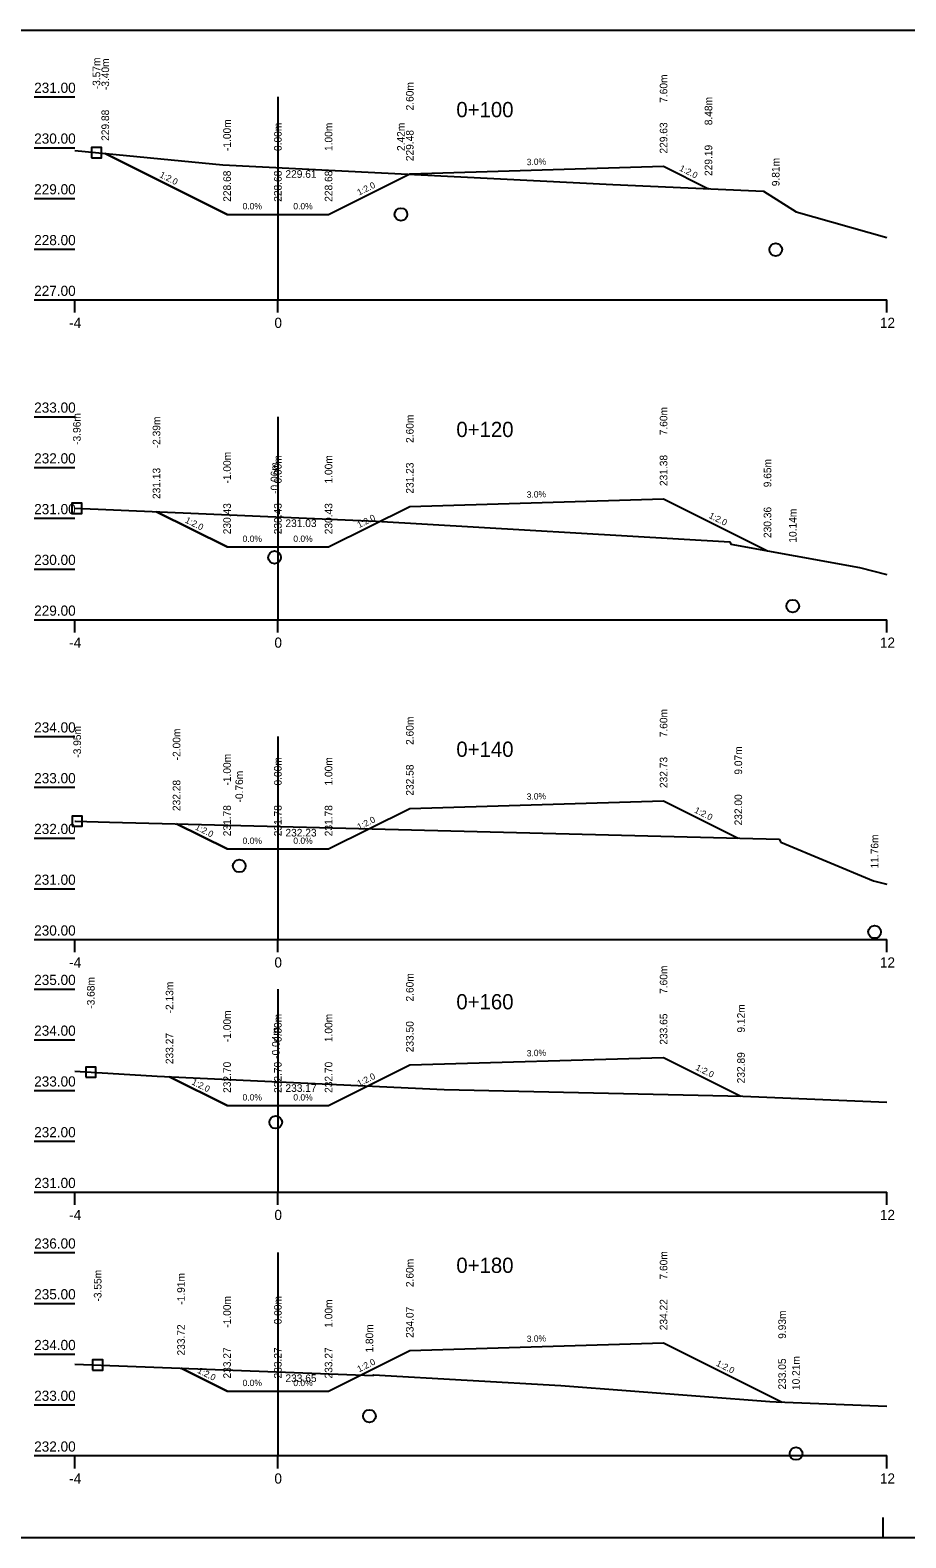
# Model space of a CAD drawing. Extents: x -578374 to -578229, y -1159997 to -1159967.
# Drawn here: x -578329.74 to -578312.48, y -1159996.88 to -1159967.18 of the extents above; entities that cross this region are included whole.
import ezdxf

# ---------------------------------------------------------------- set-up
doc = ezdxf.new("R2010")
doc.units = 0
for name, color, linetype in [('16', 7, 'Continuous'), ('21', 7, 'Continuous'), ('28', 7, 'Continuous'), ('59', 7, 'Continuous'), ('Body pricny rez', 7, 'Continuous'), ('Hranice_pozemku', 7, 'Continuous'), ('Popis pricneho profilu', 7, 'Continuous'), ('Rámy', 7, 'Continuous')]:
    doc.layers.add(name, color=color, linetype=linetype)

msp = doc.modelspace()

# ---------------------------------------------------------------- linework, layer by layer
for points in [[(-578328.857, -1159969.556), (-578325.939, -1159969.837), (-578318.26, -1159970.224), (-578315.291, -1159970.353), (-578314.648, -1159970.762), (-578312.857, -1159971.268)], [(-578328.256, -1159969.614), (-578325.857, -1159970.814), (-578324.857, -1159970.814), (-578323.857, -1159970.814), (-578322.257, -1159970.014), (-578317.257, -1159969.864), (-578316.373, -1159970.306)], [(-578325.857, -1159970.814), (-578328.256, -1159969.614)], [(-578323.857, -1159970.814), (-578322.257, -1159970.014), (-578317.257, -1159969.864)], [(-578317.257, -1159969.864), (-578316.373, -1159970.306)], [(-578316.373, -1159970.306), (-578316.373, -1159970.305), (-578316.373, -1159970.306), (-578316.373, -1159970.306), (-578316.373, -1159970.306), (-578316.372, -1159970.306), (-578316.373, -1159970.306), (-578316.372, -1159970.305)], [(-578325.857, -1159970.814), (-578324.857, -1159970.814), (-578323.857, -1159970.814)], [(-578327.247, -1159976.669), (-578325.857, -1159977.364), (-578324.857, -1159977.364), (-578323.857, -1159977.364), (-578322.257, -1159976.564), (-578317.257, -1159976.414), (-578315.21, -1159977.438)], [(-578323.857, -1159977.364), (-578322.257, -1159976.564), (-578317.257, -1159976.414)], [(-578317.257, -1159976.414), (-578315.21, -1159977.438)], [(-578328.857, -1159976.601), (-578322.922, -1159976.853), (-578315.955, -1159977.263), (-578315.93, -1159977.306), (-578313.396, -1159977.769), (-578312.857, -1159977.907)], [(-578325.857, -1159977.364), (-578327.247, -1159976.669)], [(-578325.857, -1159977.364), (-578324.857, -1159977.364), (-578323.857, -1159977.364)], [(-578315.21, -1159977.438), (-578315.211, -1159977.437), (-578315.21, -1159977.438), (-578315.211, -1159977.438), (-578315.21, -1159977.438), (-578315.21, -1159977.438), (-578315.21, -1159977.438), (-578315.21, -1159977.437)], [(-578326.852, -1159982.816), (-578325.857, -1159983.313), (-578324.857, -1159983.313), (-578323.857, -1159983.313), (-578322.257, -1159982.513), (-578317.257, -1159982.363), (-578315.785, -1159983.099)], [(-578323.857, -1159983.313), (-578322.257, -1159982.513), (-578317.257, -1159982.363)], [(-578317.257, -1159982.363), (-578315.785, -1159983.099)], [(-578328.857, -1159982.763), (-578328.845, -1159982.764), (-578328.17, -1159982.782), (-578314.983, -1159983.12), (-578314.982, -1159983.121), (-578314.945, -1159983.18), (-578313.121, -1159983.942), (-578312.857, -1159984.006)], [(-578325.857, -1159983.313), (-578326.852, -1159982.816)], [(-578315.785, -1159983.099), (-578315.786, -1159983.099), (-578315.785, -1159983.099), (-578315.786, -1159983.1), (-578315.785, -1159983.099), (-578315.785, -1159983.1), (-578315.785, -1159983.099), (-578315.785, -1159983.099)], [(-578325.857, -1159983.313), (-578324.857, -1159983.313), (-578323.857, -1159983.313)], [(-578326.991, -1159987.801), (-578325.857, -1159988.368), (-578324.857, -1159988.368), (-578323.857, -1159988.368), (-578322.257, -1159987.568), (-578317.257, -1159987.418), (-578315.732, -1159988.18)], [(-578323.857, -1159988.368), (-578322.257, -1159987.568), (-578317.257, -1159987.418)], [(-578317.257, -1159987.418), (-578315.732, -1159988.18)], [(-578328.857, -1159987.691), (-578327.236, -1159987.79), (-578321.578, -1159988.048), (-578315.696, -1159988.181), (-578312.857, -1159988.299)], [(-578325.857, -1159988.368), (-578326.991, -1159987.801)], [(-578325.857, -1159988.368), (-578324.857, -1159988.368), (-578323.857, -1159988.368)], [(-578315.732, -1159988.18), (-578315.733, -1159988.18), (-578315.732, -1159988.18), (-578315.733, -1159988.181), (-578315.732, -1159988.18), (-578315.732, -1159988.181), (-578315.732, -1159988.18), (-578315.732, -1159988.18)], [(-578326.764, -1159993.541), (-578325.857, -1159993.994), (-578324.857, -1159993.994), (-578323.857, -1159993.994), (-578322.257, -1159993.194), (-578317.257, -1159993.044), (-578314.922, -1159994.212)], [(-578323.857, -1159993.994), (-578322.257, -1159993.194), (-578317.257, -1159993.044)], [(-578317.257, -1159993.044), (-578314.922, -1159994.212)], [(-578328.857, -1159993.46), (-578322.98, -1159993.687), (-578322.973, -1159993.675), (-578319.279, -1159993.88), (-578315.161, -1159994.198), (-578315.041, -1159994.207), (-578312.857, -1159994.288)], [(-578325.857, -1159993.994), (-578326.764, -1159993.541)], [(-578325.857, -1159993.994), (-578324.857, -1159993.994), (-578323.857, -1159993.994)], [(-578314.922, -1159994.212), (-578314.923, -1159994.211), (-578314.922, -1159994.212), (-578314.923, -1159994.212), (-578314.922, -1159994.212), (-578314.922, -1159994.212), (-578314.922, -1159994.212), (-578314.922, -1159994.211)]]:
    msp.add_lwpolyline(points)
for centre in [(-578322.432, -1159970.814), (-578315.048, -1159971.507), (-578324.922, -1159977.568), (-578314.712, -1159978.529), (-578325.617, -1159983.647), (-578313.1, -1159984.947), (-578324.897, -1159988.697), (-578323.052, -1159994.484), (-578314.648, -1159995.222)]:
    msp.add_circle(centre, 0.125)
at = {"layer": '16'}
for p, q in [((-578328.857, -1159972.498), (-578312.857, -1159972.498)), ((-578328.857, -1159978.798), (-578312.857, -1159978.798)), ((-578328.857, -1159985.098), (-578312.857, -1159985.098)), ((-578328.857, -1159990.072), (-578312.857, -1159990.072)), ((-578328.857, -1159995.264), (-578312.857, -1159995.264))]:
    msp.add_line(p, q, dxfattribs=at)
at = {"layer": '21'}
for p, q in [((-578329.657, -1159968.498), (-578328.857, -1159968.498)), ((-578329.657, -1159969.498), (-578328.857, -1159969.498)), ((-578329.657, -1159970.498), (-578328.857, -1159970.498)), ((-578329.657, -1159971.498), (-578328.857, -1159971.498)), ((-578329.657, -1159972.498), (-578328.857, -1159972.498)), ((-578329.657, -1159974.798), (-578328.857, -1159974.798)), ((-578329.657, -1159975.798), (-578328.857, -1159975.798)), ((-578329.657, -1159976.798), (-578328.857, -1159976.798)), ((-578329.657, -1159977.798), (-578328.857, -1159977.798)), ((-578329.657, -1159978.798), (-578328.857, -1159978.798)), ((-578329.657, -1159981.098), (-578328.857, -1159981.098)), ((-578329.657, -1159982.098), (-578328.857, -1159982.098)), ((-578329.657, -1159983.098), (-578328.857, -1159983.098)), ((-578329.657, -1159984.098), (-578328.857, -1159984.098)), ((-578329.657, -1159985.098), (-578328.857, -1159985.098)), ((-578329.657, -1159986.072), (-578328.857, -1159986.072)), ((-578329.657, -1159987.072), (-578328.857, -1159987.072)), ((-578329.657, -1159988.072), (-578328.857, -1159988.072)), ((-578329.657, -1159989.072), (-578328.857, -1159989.072)), ((-578329.657, -1159990.072), (-578328.857, -1159990.072)), ((-578329.657, -1159991.264), (-578328.857, -1159991.264)), ((-578329.657, -1159992.264), (-578328.857, -1159992.264)), ((-578329.657, -1159993.264), (-578328.857, -1159993.264)), ((-578329.657, -1159994.264), (-578328.857, -1159994.264)), ((-578329.657, -1159995.264), (-578328.857, -1159995.264))]:
    msp.add_line(p, q, dxfattribs=at)
at = {"layer": '28'}
for p, q in [((-578324.857, -1159968.498), (-578324.857, -1159972.498)), ((-578324.857, -1159974.798), (-578324.857, -1159978.798)), ((-578324.857, -1159981.098), (-578324.857, -1159985.098)), ((-578324.857, -1159986.072), (-578324.857, -1159990.072)), ((-578324.857, -1159991.264), (-578324.857, -1159995.264))]:
    msp.add_line(p, q, dxfattribs=at)
at = {"layer": '59'}
for p, q in [((-578328.857, -1159972.748), (-578328.857, -1159972.498)), ((-578324.857, -1159972.748), (-578324.857, -1159972.498)), ((-578312.857, -1159972.748), (-578312.857, -1159972.498)), ((-578328.857, -1159979.048), (-578328.857, -1159978.798)), ((-578324.857, -1159979.048), (-578324.857, -1159978.798)), ((-578312.857, -1159979.048), (-578312.857, -1159978.798)), ((-578328.857, -1159985.348), (-578328.857, -1159985.098)), ((-578324.857, -1159985.348), (-578324.857, -1159985.098)), ((-578312.857, -1159985.348), (-578312.857, -1159985.098)), ((-578328.857, -1159990.322), (-578328.857, -1159990.072)), ((-578324.857, -1159990.322), (-578324.857, -1159990.072)), ((-578312.857, -1159990.322), (-578312.857, -1159990.072)), ((-578328.857, -1159995.514), (-578328.857, -1159995.264)), ((-578324.857, -1159995.514), (-578324.857, -1159995.264)), ((-578312.857, -1159995.514), (-578312.857, -1159995.264))]:
    msp.add_line(p, q, dxfattribs=at)
at = {"layer": 'Hranice_pozemku'}
for points in [[(-578328.53, -1159969.697), (-578328.33, -1159969.697), (-578328.33, -1159969.497), (-578328.53, -1159969.497)], [(-578328.916, -1159976.702), (-578328.716, -1159976.702), (-578328.716, -1159976.502), (-578328.916, -1159976.502)], [(-578328.909, -1159982.865), (-578328.709, -1159982.865), (-578328.709, -1159982.665), (-578328.909, -1159982.665)], [(-578328.641, -1159987.81), (-578328.441, -1159987.81), (-578328.441, -1159987.61), (-578328.641, -1159987.61)], [(-578328.506, -1159993.578), (-578328.306, -1159993.578), (-578328.306, -1159993.378), (-578328.506, -1159993.378)]]:
    msp.add_lwpolyline(points, close=True, dxfattribs=at)
at = {"layer": 'Rámy'}
msp.add_line((-578312.93, -1159996.883), (-578312.93, -1159996.483), dxfattribs=at)
msp.add_lwpolyline([(-578373.807, -1159967.183), (-578228.93, -1159967.183), (-578228.93, -1159996.883), (-578373.807, -1159996.883)], close=True, dxfattribs=at)

# ---------------------------------------------------------------- texts
for s, height, p in [('0+100', 0.3, (-578321.34, -1159968.898)), ('+', 0.001, (-578324.858, -1159970.814)), ('0+120', 0.3, (-578321.34, -1159975.198)), ('+', 0.001, (-578324.858, -1159977.365)), ('0+140', 0.3, (-578321.34, -1159981.498)), ('+', 0.001, (-578324.858, -1159983.314)), ('0+160', 0.3, (-578321.34, -1159986.472)), ('+', 0.001, (-578324.858, -1159988.368)), ('0+180', 0.3, (-578321.34, -1159991.664)), ('+', 0.001, (-578324.858, -1159993.995))]:
    msp.add_text(s, height=height).set_placement(p)
for rotation, p in [(333.4349, (-578327.199, -1159970.073)), (333.4349, (-578316.957, -1159969.944)), (26.5651, (-578323.255, -1159970.443)), (333.4349, (-578326.694, -1159976.876)), (26.5651, (-578323.255, -1159976.993)), (333.4349, (-578316.376, -1159976.785)), (333.4349, (-578316.663, -1159982.59)), (26.5651, (-578323.255, -1159982.942)), (333.4349, (-578326.497, -1159982.923)), (26.5651, (-578323.255, -1159987.997)), (333.4349, (-578316.637, -1159987.658)), (333.4349, (-578326.566, -1159987.943)), (26.5651, (-578323.255, -1159993.623)), (333.4349, (-578316.232, -1159993.487)), (333.4349, (-578326.452, -1159993.627))]:
    msp.add_text('1:2.0', height=0.125, rotation=rotation).set_placement(p)
at = {"layer": '16'}
for s, rotation, p in [('3.0%', 1.7184, (-578319.951, -1159969.844)), ('0.0%', 360, (-578325.551, -1159970.714)), ('0.0%', 360, (-578324.551, -1159970.714)), ('3.0%', 1.7184, (-578319.951, -1159976.395)), ('0.0%', 360, (-578325.551, -1159977.264)), ('0.0%', 360, (-578324.551, -1159977.264)), ('3.0%', 1.7184, (-578319.951, -1159982.344)), ('0.0%', 360, (-578325.551, -1159983.213)), ('0.0%', 360, (-578324.551, -1159983.213)), ('3.0%', 1.7184, (-578319.951, -1159987.399)), ('0.0%', 360, (-578325.551, -1159988.268)), ('0.0%', 360, (-578324.551, -1159988.268)), ('3.0%', 1.7184, (-578319.951, -1159993.025)), ('0.0%', 360, (-578325.551, -1159993.894)), ('0.0%', 360, (-578324.551, -1159993.894))]:
    msp.add_text(s, height=0.125, rotation=rotation, dxfattribs=at).set_placement(p)
at = {"layer": '21'}
for s, p in [('231.00', (-578329.657, -1159968.418)), ('230.00', (-578329.657, -1159969.418)), ('229.00', (-578329.657, -1159970.418)), ('228.00', (-578329.657, -1159971.418)), ('227.00', (-578329.657, -1159972.418)), ('-4', (-578328.967, -1159973.048)), ('0', (-578324.924, -1159973.048)), ('12', (-578312.995, -1159973.048)), ('233.00', (-578329.657, -1159974.718)), ('232.00', (-578329.657, -1159975.718)), ('231.00', (-578329.657, -1159976.718)), ('230.00', (-578329.657, -1159977.718)), ('229.00', (-578329.657, -1159978.718)), ('-4', (-578328.967, -1159979.348)), ('0', (-578324.924, -1159979.348)), ('12', (-578312.995, -1159979.348)), ('234.00', (-578329.657, -1159981.018)), ('233.00', (-578329.657, -1159982.018)), ('232.00', (-578329.657, -1159983.018)), ('231.00', (-578329.657, -1159984.018)), ('230.00', (-578329.657, -1159985.018)), ('-4', (-578328.967, -1159985.648)), ('0', (-578324.924, -1159985.648)), ('12', (-578312.995, -1159985.648)), ('235.00', (-578329.657, -1159985.992)), ('234.00', (-578329.657, -1159986.992)), ('233.00', (-578329.657, -1159987.992)), ('232.00', (-578329.657, -1159988.992)), ('231.00', (-578329.657, -1159989.992)), ('-4', (-578328.967, -1159990.622)), ('0', (-578324.924, -1159990.622)), ('12', (-578312.995, -1159990.622)), ('236.00', (-578329.657, -1159991.184)), ('235.00', (-578329.657, -1159992.184)), ('234.00', (-578329.657, -1159993.184)), ('233.00', (-578329.657, -1159994.184)), ('232.00', (-578329.657, -1159995.184)), ('-4', (-578328.967, -1159995.814)), ('0', (-578324.924, -1159995.814)), ('12', (-578312.995, -1159995.814))]:
    msp.add_text(s, height=0.2, dxfattribs=at).set_placement(p)
at = {"layer": '59'}
for s, p in [('229.61', (-578324.707, -1159970.092)), ('231.03', (-578324.707, -1159976.971)), ('232.23', (-578324.707, -1159983.067)), ('233.17', (-578324.707, -1159988.098)), ('233.65', (-578324.707, -1159993.814))]:
    msp.add_text(s, height=0.15, dxfattribs=at).set_placement(p)
at = {"layer": 'Body pricny rez'}
for p in [(-578328.257, -1159969.614), (-578322.258, -1159970.014), (-578317.258, -1159969.864), (-578325.858, -1159970.814), (-578323.858, -1159970.814), (-578322.258, -1159976.565), (-578317.258, -1159976.415), (-578327.248, -1159976.67), (-578325.858, -1159977.365), (-578323.858, -1159977.365), (-578317.258, -1159982.364), (-578322.258, -1159982.514), (-578326.853, -1159982.816), (-578325.858, -1159983.314), (-578323.858, -1159983.314), (-578317.258, -1159987.418), (-578326.992, -1159987.801), (-578322.258, -1159987.568), (-578325.858, -1159988.368), (-578323.858, -1159988.368), (-578322.258, -1159993.195), (-578317.258, -1159993.045), (-578326.764, -1159993.541), (-578325.858, -1159993.995), (-578323.858, -1159993.995)]:
    msp.add_text('+', height=0.001, dxfattribs=at).set_placement(p)
at = {"layer": 'Popis pricneho profilu'}
for s, p in [('-3.57m', (-578328.355, -1159968.347)), ('-3.40m', (-578328.181, -1159968.364)), ('2.60m', (-578322.182, -1159968.764)), ('7.60m', (-578317.182, -1159968.614)), ('8.48m', (-578316.298, -1159969.056)), ('229.88', (-578328.181, -1159969.364)), ('-1.00m', (-578325.782, -1159969.564)), ('0.00m', (-578324.782, -1159969.564)), ('1.00m', (-578323.782, -1159969.564)), ('2.42m', (-578322.357, -1159969.564)), ('229.63', (-578317.182, -1159969.614)), ('229.48', (-578322.182, -1159969.764)), ('229.19', (-578316.298, -1159970.056)), ('9.81m', (-578314.973, -1159970.257)), ('228.68', (-578325.782, -1159970.564)), ('228.68', (-578324.782, -1159970.564)), ('228.68', (-578323.782, -1159970.564)), ('-3.96m', (-578328.741, -1159975.352)), ('2.60m', (-578322.182, -1159975.314)), ('7.60m', (-578317.182, -1159975.164)), ('-2.39m', (-578327.172, -1159975.419)), ('-1.00m', (-578325.782, -1159976.114)), ('0.00m', (-578324.782, -1159976.114)), ('1.00m', (-578323.782, -1159976.114)), ('231.38', (-578317.182, -1159976.164)), ('9.65m', (-578315.135, -1159976.188)), ('231.13', (-578327.172, -1159976.419)), ('-0.06m', (-578324.847, -1159976.318)), ('231.23', (-578322.182, -1159976.314)), ('230.43', (-578325.782, -1159977.114)), ('230.43', (-578324.782, -1159977.114)), ('230.43', (-578323.782, -1159977.114)), ('230.36', (-578315.135, -1159977.188)), ('10.14m', (-578314.637, -1159977.279)), ('2.60m', (-578322.182, -1159981.263)), ('7.60m', (-578317.182, -1159981.113)), ('-3.95m', (-578328.734, -1159981.515)), ('-2.00m', (-578326.777, -1159981.566)), ('9.07m', (-578315.71, -1159981.849)), ('-1.00m', (-578325.782, -1159982.063)), ('0.00m', (-578324.782, -1159982.063)), ('1.00m', (-578323.782, -1159982.063)), ('232.73', (-578317.182, -1159982.113)), ('-0.76m', (-578325.542, -1159982.397)), ('232.58', (-578322.182, -1159982.263)), ('232.28', (-578326.777, -1159982.566)), ('231.78', (-578325.782, -1159983.063)), ('231.78', (-578324.782, -1159983.063)), ('231.78', (-578323.782, -1159983.063)), ('232.00', (-578315.71, -1159982.849)), ('11.76m', (-578313.025, -1159983.697)), ('7.60m', (-578317.182, -1159986.168)), ('-3.68m', (-578328.466, -1159986.46)), ('-2.13m', (-578326.916, -1159986.551)), ('2.60m', (-578322.182, -1159986.318)), ('-1.00m', (-578325.782, -1159987.118)), ('0.00m', (-578324.782, -1159987.118)), ('1.00m', (-578323.782, -1159987.118)), ('233.65', (-578317.182, -1159987.168)), ('9.12m', (-578315.657, -1159986.93)), ('233.27', (-578326.916, -1159987.551)), ('-0.04m', (-578324.822, -1159987.447)), ('233.50', (-578322.182, -1159987.318)), ('232.70', (-578325.782, -1159988.118)), ('232.70', (-578324.782, -1159988.118)), ('232.70', (-578323.782, -1159988.118)), ('232.89', (-578315.657, -1159987.93)), ('2.60m', (-578322.182, -1159991.944)), ('7.60m', (-578317.182, -1159991.794)), ('-3.55m', (-578328.331, -1159992.228)), ('-1.91m', (-578326.689, -1159992.291)), ('-1.00m', (-578325.782, -1159992.744)), ('-0.00m', (-578324.782, -1159992.744)), ('1.00m', (-578323.782, -1159992.744)), ('234.22', (-578317.182, -1159992.794)), ('234.07', (-578322.182, -1159992.944)), ('9.93m', (-578314.847, -1159992.962)), ('233.72', (-578326.689, -1159993.291)), ('1.80m', (-578322.977, -1159993.234)), ('233.27', (-578325.782, -1159993.744)), ('233.27', (-578324.782, -1159993.744)), ('233.27', (-578323.782, -1159993.744)), ('233.05', (-578314.847, -1159993.962)), ('10.21m', (-578314.573, -1159993.972))]:
    msp.add_text(s, height=0.15, rotation=90, dxfattribs=at).set_placement(p)

doc.saveas('drawing.dxf')
